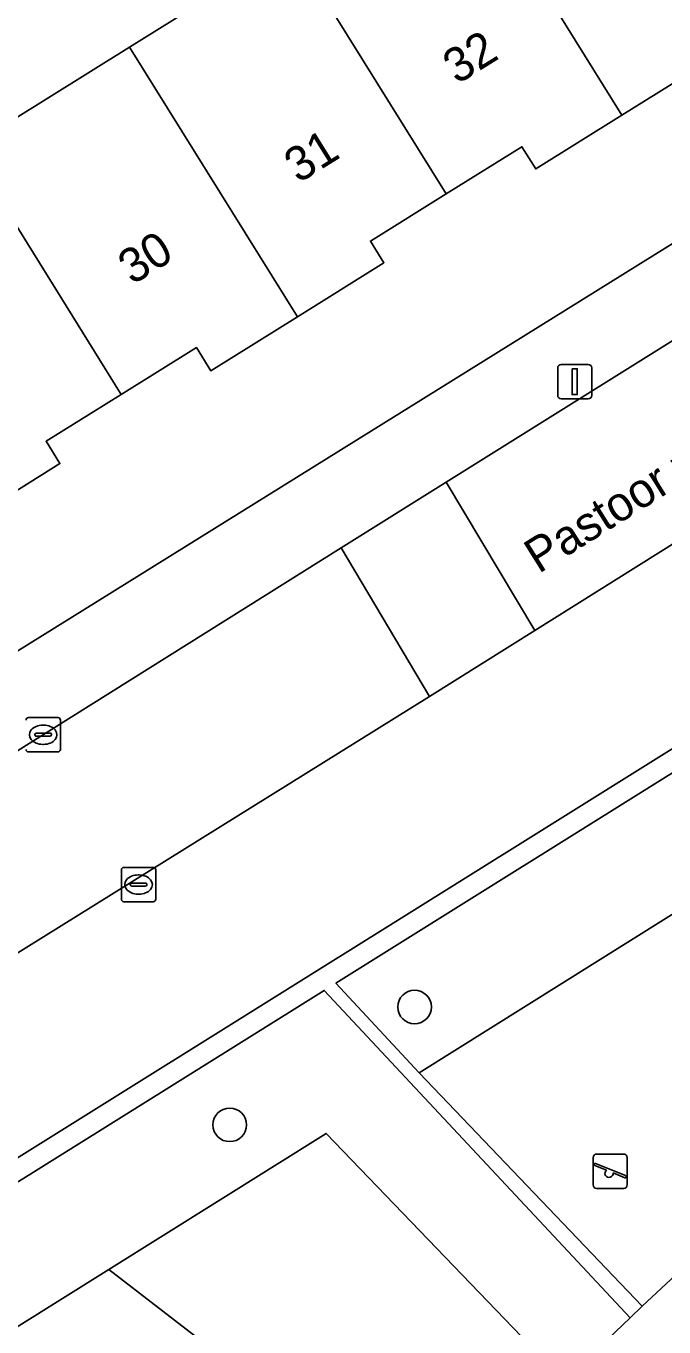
# Model space of a CAD drawing. Extents: x 159664 to 160323, y 385312 to 386115.
# Drawn here: x 160010.7 to 160029.26, y 385486.85 to 385524.69 of the extents above; entities that cross this region are included whole.
import ezdxf

# ---------------------------------------------------------------- set-up
doc = ezdxf.new("R2010")
doc.units = 0
for name, color, linetype in [('IMGEO_Boom', 7, 'Continuous'), ('IMGEO_Erf', 7, 'Continuous'), ('IMGEO_Groenvoorziening', 7, 'Continuous'), ('IMGEO_Haag', 7, 'Continuous'), ('IMGEO_Kolk', 7, 'Continuous'), ('IMGEO_Lichtmast', 7, 'Continuous'), ('IMGEO_Openbare_ruimte_label', 7, 'Continuous'), ('IMGEO_Pand', 7, 'Continuous'), ('IMGEO_Pand_nummerreeks', 7, 'Continuous'), ('IMGEO_Parkeervlak_open', 7, 'Continuous'), ('IMGEO_Rijbaan_lokaal_open', 7, 'Continuous'), ('IMGEO_Speelvoorziening', 7, 'Continuous'), ('IMGEO_Voetpad_halfverhard', 7, 'Continuous'), ('IMGEO_Voetpad_open', 7, 'Continuous')]:
    doc.layers.add(name, color=color, linetype=linetype)

msp = doc.modelspace()

# ---------------------------------------------------------------- linework, layer by layer
at = {"layer": 'IMGEO_Boom'}
for centre in [(160022.006, 385496.159), (160016.628, 385492.73)]:
    msp.add_circle(centre, 0.489, dxfattribs=at)
at = {"layer": 'IMGEO_Erf'}
for points in [[(160000, 385500.022), (160053.732, 385533.435)], [(160009.001, 385521.149), (160013.709, 385524.082), (160018.436, 385527.026)], [(160032.325, 385525.73), (160030.119, 385524.355), (160030.549, 385523.664), (160028.04, 385522.101), (160025.53, 385520.538), (160025.128, 385521.184), (160022.926, 385519.812), (160020.721, 385518.439), (160021.114, 385517.808), (160018.595, 385516.239), (160016.073, 385514.668), (160015.655, 385515.339), (160013.469, 385513.977), (160011.282, 385512.615), (160011.687, 385511.964), (160009.162, 385510.392)]]:
    msp.add_lwpolyline(points, dxfattribs=at)
at = {"layer": 'IMGEO_Groenvoorziening'}
for points in [[(160041.927, 385510.723), (160041.439, 385511.126), (160002.943, 385487.083), (160000.956, 385485.842), (160003.152, 385482.295), (160003.661, 385482.613), (160001.781, 385485.649), (160019.378, 385496.639), (160028.275, 385487.118), (160028.631, 385487.46), (160022.143, 385494.244), (160019.717, 385496.851), (160041.542, 385510.482), (160044.219, 385508.203), (160044.649, 385508.478)], [(160044.219, 385508.203), (160041.542, 385510.482), (160019.717, 385496.851), (160022.143, 385494.244), (160032.443, 385500.689)], [(160019.378, 385496.639), (160001.781, 385485.649), (160003.661, 385482.613), (160013.113, 385488.526), (160019.436, 385492.482), (160026.357, 385485.279), (160028.275, 385487.118)], [(160019.436, 385492.482), (160013.113, 385488.526), (160022.326, 385481.412), (160026.357, 385485.279)]]:
    msp.add_lwpolyline(points, close=True, dxfattribs=at)
at = {"layer": 'IMGEO_Haag'}
msp.add_lwpolyline([(160019.717, 385496.851), (160041.542, 385510.482), (160044.219, 385508.203), (160044.649, 385508.478), (160041.927, 385510.723), (160041.439, 385511.126), (160002.943, 385487.083), (160000.956, 385485.842), (160003.152, 385482.295), (160003.661, 385482.613), (160001.781, 385485.649), (160019.378, 385496.639), (160028.275, 385487.118), (160028.631, 385487.46), (160022.143, 385494.244)], close=True, dxfattribs=at)
at = {"layer": 'IMGEO_Kolk'}
for p, q in [((160010.773, 385504.578), (160011.625, 385504.578)), ((160011.699, 385504.504), (160011.699, 385503.652)), ((160010.957, 385504.072), (160010.957, 385504.084)), ((160011.395, 385504.035), (160010.997, 385504.035)), ((160011, 385504.121), (160011.398, 385504.121)), ((160011.186, 385504.358), (160011.211, 385504.358)), ((160011.441, 385504.084), (160011.441, 385504.072)), ((160011.209, 385503.798), (160011.184, 385503.798)), ((160011.625, 385503.578), (160010.773, 385503.578)), ((160013.549, 385500.22), (160014.401, 385500.22)), ((160013.474, 385499.294), (160013.474, 385500.146)), ((160013.962, 385500), (160013.987, 385500)), ((160014.475, 385500.146), (160014.475, 385499.294)), ((160013.733, 385499.714), (160013.733, 385499.726)), ((160014.171, 385499.677), (160013.773, 385499.677)), ((160013.776, 385499.763), (160014.174, 385499.763)), ((160014.217, 385499.726), (160014.217, 385499.714)), ((160014.401, 385499.22), (160013.549, 385499.22)), ((160013.985, 385499.44), (160013.96, 385499.44))]:
    msp.add_line(p, q, dxfattribs=at)
for points in [[(160010.773, 385504.578), (160011.625, 385504.578)], [(160011.699, 385504.504), (160011.699, 385503.652)], [(160011.625, 385503.578), (160010.773, 385503.578)], [(160013.549, 385500.22), (160014.401, 385500.22)], [(160013.474, 385499.294), (160013.474, 385500.146)], [(160014.475, 385500.146), (160014.475, 385499.294)], [(160014.401, 385499.22), (160013.549, 385499.22)]]:
    msp.add_lwpolyline(points, dxfattribs=at)
for centre, radius, start, end in [((160010.775, 385504.502), 0.0765, 91.552, 178.448), ((160010.775, 385504.502), 0.0765, 91.552, 178.448), ((160011.623, 385504.502), 0.0765, 1.552, 88.448), ((160011.623, 385504.502), 0.0765, 1.552, 88.448), ((160010.997, 385504.081), 0.0403, 85.8775, 175.7526), ((160010.994, 385504.071), 0.0366, 178.938, 274.7102), ((160011.398, 385504.078), 0.043, 264.8664, 352.4533), ((160011.402, 385504.083), 0.0386, 1.7309, 96.639), ((160010.775, 385503.654), 0.0765, 181.552, 268.448), ((160010.775, 385503.654), 0.0765, 181.552, 268.448), ((160011.623, 385503.654), 0.0765, 271.552, 358.448), ((160011.623, 385503.654), 0.0765, 271.552, 358.448), ((160013.551, 385500.144), 0.0765, 91.552, 178.448), ((160013.551, 385500.144), 0.0765, 91.552, 178.448), ((160014.399, 385500.144), 0.0765, 1.552, 88.448), ((160014.399, 385500.144), 0.0765, 1.552, 88.448), ((160013.773, 385499.723), 0.0403, 85.8775, 175.7526), ((160013.77, 385499.713), 0.0366, 178.938, 274.7102), ((160014.174, 385499.72), 0.043, 264.8664, 352.4533), ((160014.178, 385499.725), 0.0386, 1.7309, 96.639), ((160013.551, 385499.296), 0.0765, 181.552, 268.448), ((160013.551, 385499.296), 0.0765, 181.552, 268.448), ((160014.399, 385499.296), 0.0765, 271.552, 358.448), ((160014.399, 385499.296), 0.0765, 271.552, 358.448)]:
    msp.add_arc(centre, radius, start, end, dxfattribs=at)
for centre, major_axis, ratio, start_param, end_param in [((160011.185, 385504.078), (-0.387, 0.002), 0.722429, 4.712389, 7.853982), ((160011.21, 385504.078), (-0.39, 0.002), 0.717154, 1.570796, 4.712389), ((160013.961, 385499.72), (-0.387, 0.002), 0.722429, 4.712389, 7.853982), ((160013.986, 385499.72), (-0.39, 0.002), 0.717154, 1.570796, 4.712389)]:
    msp.add_ellipse(centre, major_axis=major_axis, ratio=ratio, start_param=start_param, end_param=end_param, dxfattribs=at)
at = {"layer": 'IMGEO_Lichtmast'}
for p, q in [((160026.17, 385513.949), (160026.17, 385514.749)), ((160026.17, 385514.749), (160026.17, 385513.949)), ((160026.27, 385514.849), (160027.06, 385514.849)), ((160027.06, 385514.849), (160026.27, 385514.849)), ((160027.16, 385514.749), (160027.16, 385513.949)), ((160027.16, 385513.949), (160027.16, 385514.749)), ((160027.06, 385513.849), (160026.27, 385513.849)), ((160026.27, 385513.849), (160027.06, 385513.849))]:
    msp.add_line(p, q, dxfattribs=at)
msp.add_lwpolyline([(160026.59, 385514.724), (160026.74, 385514.724), (160026.74, 385513.974), (160026.59, 385513.974), (160026.59, 385514.724)], dxfattribs=at)
for centre, start, end in [((160026.27, 385514.749), 90, 180), ((160026.27, 385514.749), 90, 180), ((160027.06, 385514.749), 0, 90), ((160027.06, 385514.749), 360, 90), ((160026.27, 385513.949), 180, 270), ((160026.27, 385513.949), 180, 270), ((160027.06, 385513.949), 270, 0), ((160027.06, 385513.949), 270, 0)]:
    msp.add_arc(centre, 0.1, start, end, dxfattribs=at)
at = {"layer": 'IMGEO_Pand'}
for points in [[(160023.148, 385529.961), (160028.04, 385522.101), (160030.549, 385523.664), (160030.119, 385524.355), (160032.325, 385525.73), (160027.858, 385532.894), (160026.332, 385535.341), (160024.377, 385534.121), (160025.902, 385531.676)], [(160022.926, 385519.812), (160025.128, 385521.184), (160025.53, 385520.538), (160028.04, 385522.101), (160023.148, 385529.961), (160018.436, 385527.026)], [(160018.595, 385516.239), (160021.114, 385517.808), (160020.721, 385518.439), (160022.926, 385519.812), (160018.436, 385527.026), (160013.709, 385524.082)], [(160013.469, 385513.977), (160015.655, 385515.339), (160016.073, 385514.668), (160018.595, 385516.239), (160013.709, 385524.082), (160009.001, 385521.149)], [(160007.473, 385523.602), (160002.758, 385520.665), (160004.287, 385518.213), (160009.162, 385510.392), (160011.687, 385511.964), (160011.282, 385512.615), (160013.469, 385513.977), (160009.001, 385521.149)]]:
    msp.add_lwpolyline(points, close=True, dxfattribs=at)
at = {"layer": 'IMGEO_Parkeervlak_open'}
for points in [[(160041.008, 385516.825), (160025.502, 385507.11), (160022.435, 385505.195), (160001.509, 385492.171)], [(160002.943, 385487.083), (160041.439, 385511.126), (160040.846, 385516.449)]]:
    msp.add_lwpolyline(points, dxfattribs=at)
at = {"layer": 'IMGEO_Rijbaan_lokaal_open'}
for points in [[(160050.118, 385528.392), (160044.889, 385525.15), (160022.924, 385511.421), (160025.502, 385507.11), (160041.008, 385516.825), (160042.28, 385517.631), (160053.613, 385524.691), (160055.564, 385525.915), (160052.915, 385530.146)], [(160019.873, 385509.513), (160022.435, 385505.195), (160025.502, 385507.11), (160022.924, 385511.421)]]:
    msp.add_lwpolyline(points, close=True, dxfattribs=at)
msp.add_lwpolyline([(159999.29, 385490.746), (160001.509, 385492.171), (160022.435, 385505.195), (160019.873, 385509.513), (159989.006, 385490.171), (159988.172, 385489.645), (159987.726, 385487.201), (159987.957, 385486.832), (159994.242, 385476.725), (159998.386, 385479.297), (159997.177, 385481.209)], dxfattribs=at)
at = {"layer": 'IMGEO_Speelvoorziening'}
for p, q in [((160027.303, 385491.881), (160028.093, 385491.881)), ((160028.093, 385491.881), (160027.303, 385491.881)), ((160027.203, 385490.981), (160027.203, 385491.781)), ((160027.203, 385491.781), (160027.203, 385490.981)), ((160027.586, 385491.409), (160027.247, 385491.546)), ((160027.272, 385491.606), (160028.148, 385491.253)), ((160028.193, 385491.781), (160028.193, 385490.981)), ((160028.193, 385490.981), (160028.193, 385491.781)), ((160028.124, 385491.193), (160027.784, 385491.33)), ((160028.093, 385490.881), (160027.303, 385490.881)), ((160027.303, 385490.881), (160028.093, 385490.881))]:
    msp.add_line(p, q, dxfattribs=at)
for centre, radius, start, end in [((160027.303, 385491.781), 0.1, 90, 180), ((160027.303, 385491.781), 0.1, 90, 180), ((160028.093, 385491.781), 0.1, 0, 90), ((160028.093, 385491.781), 0.1, 360, 90), ((160027.26, 385491.576), 0.0327, 68.078, 248.078), ((160027.665, 385491.319), 0.12, 130.9928, 5.1632), ((160028.136, 385491.223), 0.0327, 248.078, 68.078), ((160027.303, 385490.981), 0.1, 180, 270), ((160027.303, 385490.981), 0.1, 180, 270), ((160028.093, 385490.981), 0.1, 270, 0), ((160028.093, 385490.981), 0.1, 270, 0)]:
    msp.add_arc(centre, radius, start, end, dxfattribs=at)
at = {"layer": 'IMGEO_Voetpad_halfverhard'}
msp.add_lwpolyline([(160059.444, 385516.962), (160058.192, 385515.766), (160049.727, 385507.676), (160049.169, 385507.152), (160046.608, 385509.334), (160043.201, 385512.238), (160041.439, 385511.126), (160041.927, 385510.723), (160044.649, 385508.478), (160047.831, 385505.853), (160047.417, 385505.481), (160046.859, 385504.98), (160045.426, 385503.693), (160037.207, 385495.716), (160034.67, 385493.254), (160034.63, 385493.216), (160030.305, 385489.018), (160028.631, 385487.46), (160028.275, 385487.118), (160026.357, 385485.279), (160022.326, 385481.412), (160013.113, 385488.526), (160003.661, 385482.613)], dxfattribs=at)
at = {"layer": 'IMGEO_Voetpad_open'}
for points in [[(160044.889, 385525.15), (160044.326, 385526.087), (160049.515, 385529.3), (160050.118, 385528.392), (160052.915, 385530.146), (160054.445, 385531.102), (160053.732, 385533.435), (160000, 385500.022), (159984.417, 385490.391), (159986.593, 385489.674), (159989.006, 385490.171), (160019.873, 385509.513), (160022.924, 385511.421)], [(160037.207, 385495.716), (160032.443, 385500.689), (160022.143, 385494.244), (160028.631, 385487.46), (160030.305, 385489.018), (160034.63, 385493.216), (160034.67, 385493.254)]]:
    msp.add_lwpolyline(points, close=True, dxfattribs=at)

# ---------------------------------------------------------------- texts
at = {"layer": 'IMGEO_Openbare_ruimte_label'}
msp.add_text('Pastoor van Arsplein', height=1, rotation=32.0054, dxfattribs=at).set_placement((160025.615, 385508.75))
at = {"layer": 'IMGEO_Pand_nummerreeks'}
for s, rotation, p in [('32', 31.9177, (160023.244, 385522.98)), ('31', 31.9177, (160018.626, 385520.103)), ('30', 31.9193, (160013.792, 385517.147))]:
    msp.add_text(s, height=1, rotation=rotation, dxfattribs=at).set_placement(p)

doc.saveas('drawing.dxf')
